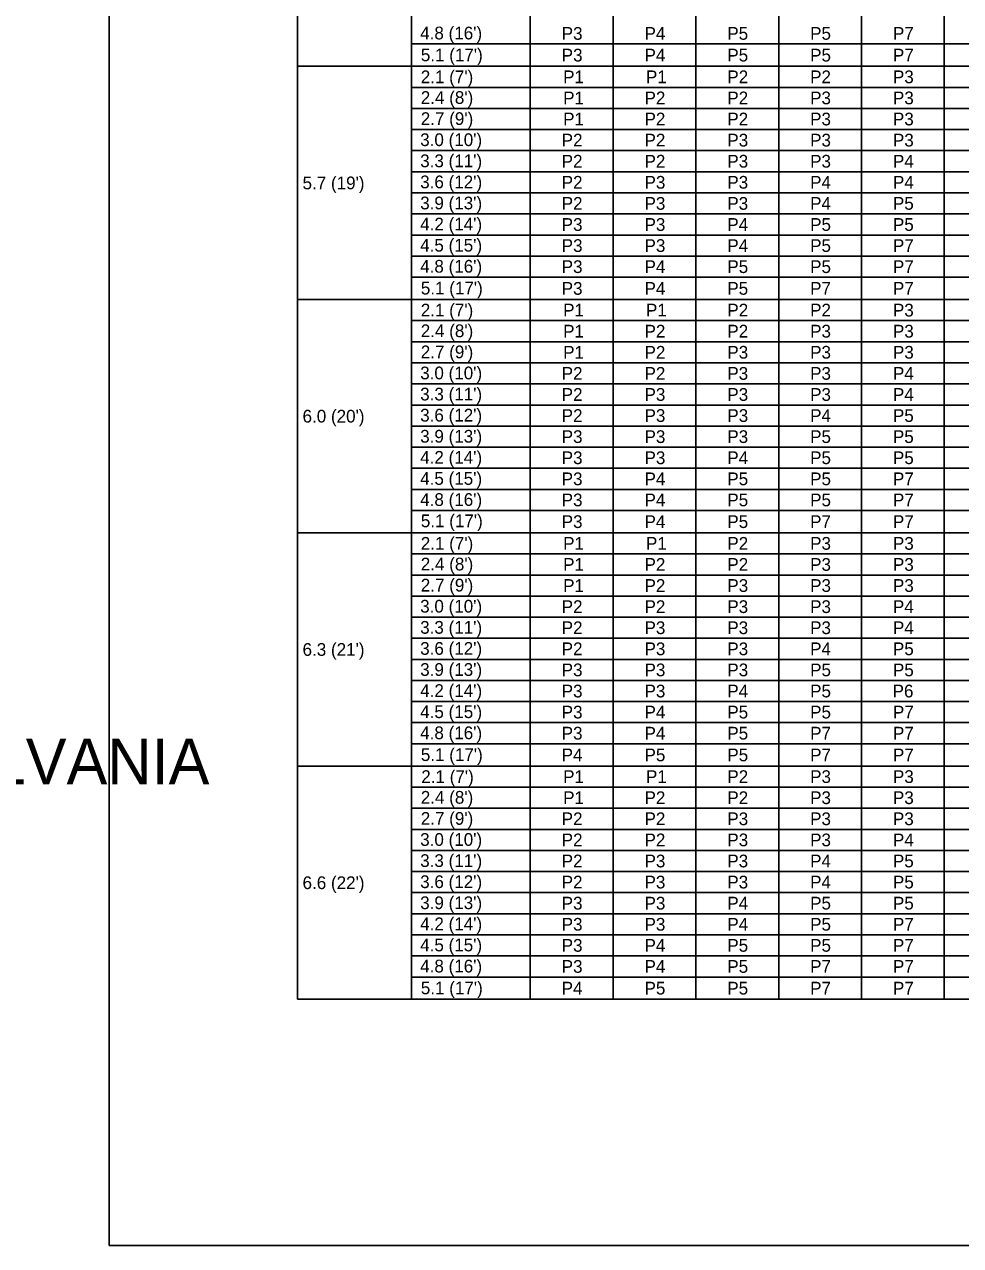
# Model space of a CAD drawing. Extents: x 637580 to 641008, y 294594 to 295782.
# Drawn here: x 639282.3 to 639502.8, y 295202.6 to 295490.5 of the extents above; entities that cross this region are included whole.
import ezdxf

# ---------------------------------------------------------------- set-up
doc = ezdxf.new("R2010")
doc.units = 0
doc.layers.add('1', color=7, linetype='Continuous')
doc.layers.add('2', color=7, linetype='Continuous')

msp = doc.modelspace()

# ---------------------------------------------------------------- linework, layer by layer
at = {"layer": '1'}
for p, q in [((639302.31, 295766.63), (639302.31, 295202.63)), ((639346.67, 295260.68), (639346.67, 295724.98)), ((639373.47, 295260.68), (639373.47, 295717.3)), ((639401.48, 295260.68), (639401.48, 295717.3)), ((639346.67, 295480.64), (639713.6, 295480.64)), ((639346.67, 295425.65), (639713.6, 295425.65)), ((639346.67, 295370.66), (639713.6, 295370.66)), ((639346.67, 295315.67), (639713.6, 295315.67)), ((639346.67, 295260.68), (639713.6, 295260.68)), ((640088.31, 295202.63), (639302.31, 295202.63)), ((639302.31, 295202.63), (639888.31, 295202.63))]:
    msp.add_line(p, q, dxfattribs=at)
at = {"layer": '2'}
for p, q in [((639401.48, 295260.68), (639401.48, 295717.3)), ((639420.98, 295260.68), (639420.98, 295709.96)), ((639440.49, 295260.68), (639440.49, 295709.96)), ((639460, 295260.68), (639460, 295709.96)), ((639479.51, 295260.68), (639479.51, 295709.96)), ((639499.01, 295260.68), (639499.01, 295709.96)), ((639373.47, 295485.9), (639713.6, 295485.9)), ((639373.47, 295475.66), (639713.6, 295475.66)), ((639373.47, 295470.69), (639713.6, 295470.69)), ((639373.47, 295465.72), (639713.6, 295465.72)), ((639373.47, 295460.75), (639713.6, 295460.75)), ((639373.47, 295455.77), (639713.6, 295455.77)), ((639373.47, 295450.8), (639713.6, 295450.8)), ((639373.47, 295445.83), (639713.6, 295445.83)), ((639373.47, 295440.86), (639713.6, 295440.86)), ((639373.47, 295435.88), (639713.6, 295435.88)), ((639373.47, 295430.91), (639713.6, 295430.91)), ((639373.47, 295420.67), (639713.6, 295420.67)), ((639373.47, 295415.7), (639713.6, 295415.7)), ((639373.47, 295410.73), (639713.6, 295410.73)), ((639373.47, 295405.76), (639713.6, 295405.76)), ((639373.47, 295400.78), (639713.6, 295400.78)), ((639373.47, 295395.81), (639713.6, 295395.81)), ((639373.47, 295390.84), (639713.6, 295390.84)), ((639373.47, 295385.87), (639713.6, 295385.87)), ((639373.47, 295380.89), (639713.6, 295380.89)), ((639373.47, 295375.92), (639713.6, 295375.92)), ((639373.47, 295365.68), (639713.6, 295365.68)), ((639373.47, 295360.71), (639713.6, 295360.71)), ((639373.47, 295355.74), (639713.6, 295355.74)), ((639373.47, 295350.77), (639713.6, 295350.77)), ((639373.47, 295345.79), (639713.6, 295345.79)), ((639373.47, 295340.82), (639713.6, 295340.82)), ((639373.47, 295335.85), (639713.6, 295335.85)), ((639373.47, 295330.88), (639713.6, 295330.88)), ((639373.47, 295325.9), (639713.6, 295325.9)), ((639373.47, 295320.93), (639713.6, 295320.93)), ((639373.47, 295310.69), (639713.6, 295310.69)), ((639373.47, 295305.72), (639713.6, 295305.72)), ((639373.47, 295300.75), (639713.6, 295300.75)), ((639373.47, 295295.78), (639713.6, 295295.78)), ((639373.47, 295290.8), (639713.6, 295290.8)), ((639373.47, 295285.83), (639713.6, 295285.83)), ((639373.47, 295280.86), (639713.6, 295280.86)), ((639373.47, 295275.89), (639713.6, 295275.89)), ((639373.47, 295270.91), (639713.6, 295270.91)), ((639373.47, 295265.94), (639713.6, 295265.94))]:
    msp.add_line(p, q, dxfattribs=at)

# ---------------------------------------------------------------- texts
at = {"layer": '1'}
for s, height, p in [("4.8 (16')", 3, (639375.54, 295486.98)), ('P3', 3, (639408.88, 295486.89)), ('P4', 3, (639428.39, 295486.89)), ('P5', 3, (639447.9, 295486.89)), ('P5', 3, (639467.4, 295486.89)), ('P7', 3, (639486.91, 295486.89)), ("5.1 (17')", 3, (639375.69, 295481.83)), ('P3', 3, (639408.88, 295481.77)), ('P4', 3, (639428.39, 295481.77)), ('P5', 3, (639447.9, 295481.77)), ('P5', 3, (639467.4, 295481.77)), ('P7', 3, (639486.91, 295481.77)), ("2.1 (7')", 3, (639375.68, 295476.65)), ('P1', 3, (639409.22, 295476.65)), ('P1', 3, (639428.73, 295476.65)), ('P2', 3, (639447.9, 295476.65)), ('P2', 3, (639467.4, 295476.65)), ('P3', 3, (639486.91, 295476.65)), ("2.4 (8')", 3, (639375.68, 295471.77)), ('P1', 3, (639409.22, 295471.68)), ('P2', 3, (639428.39, 295471.68)), ('P2', 3, (639447.9, 295471.68)), ('P3', 3, (639467.4, 295471.68)), ('P3', 3, (639486.91, 295471.68)), ("2.7 (9')", 3, (639375.68, 295466.8)), ('P1', 3, (639409.22, 295466.71)), ('P2', 3, (639428.39, 295466.71)), ('P2', 3, (639447.9, 295466.71)), ('P3', 3, (639467.4, 295466.71)), ('P3', 3, (639486.91, 295466.71)), ("3.0 (10')", 3, (639375.54, 295461.83)), ('P2', 3, (639408.88, 295461.73)), ('P2', 3, (639428.39, 295461.73)), ('P3', 3, (639447.9, 295461.73)), ('P3', 3, (639467.4, 295461.73)), ('P3', 3, (639486.91, 295461.73)), ("3.3 (11')", 3, (639375.54, 295456.85)), ('P2', 3, (639408.88, 295456.76)), ('P2', 3, (639428.39, 295456.76)), ('P3', 3, (639447.9, 295456.76)), ('P3', 3, (639467.4, 295456.76)), ('P4', 3, (639486.91, 295456.76)), ("5.7 (19')", 3, (639347.83, 295451.64)), ("3.6 (12')", 3, (639375.54, 295451.88)), ('P2', 3, (639408.88, 295451.79)), ('P3', 3, (639428.39, 295451.79)), ('P3', 3, (639447.9, 295451.79)), ('P4', 3, (639467.4, 295451.79)), ('P4', 3, (639486.91, 295451.79)), ("3.9 (13')", 3, (639375.54, 295446.91)), ('P2', 3, (639408.88, 295446.82)), ('P3', 3, (639428.39, 295446.82)), ('P3', 3, (639447.9, 295446.82)), ('P4', 3, (639467.4, 295446.82)), ('P5', 3, (639486.91, 295446.82)), ("4.2 (14')", 3, (639375.54, 295441.94)), ('P3', 3, (639408.88, 295441.84)), ('P3', 3, (639428.39, 295441.84)), ('P4', 3, (639447.9, 295441.84)), ('P5', 3, (639467.4, 295441.84)), ('P5', 3, (639486.91, 295441.84)), ("4.5 (15')", 3, (639375.54, 295436.96)), ('P3', 3, (639408.88, 295436.87)), ('P3', 3, (639428.39, 295436.87)), ('P4', 3, (639447.9, 295436.87)), ('P5', 3, (639467.4, 295436.87)), ('P7', 3, (639486.91, 295436.87)), ("4.8 (16')", 3, (639375.54, 295431.99)), ('P3', 3, (639408.88, 295431.9)), ('P4', 3, (639428.39, 295431.9)), ('P5', 3, (639447.9, 295431.9)), ('P5', 3, (639467.4, 295431.9)), ('P7', 3, (639486.91, 295431.9)), ("5.1 (17')", 3, (639375.69, 295426.84)), ('P3', 3, (639408.88, 295426.78)), ('P4', 3, (639428.39, 295426.78)), ('P5', 3, (639447.9, 295426.78)), ('P7', 3, (639467.4, 295426.78)), ('P7', 3, (639486.91, 295426.78)), ("2.1 (7')", 3, (639375.68, 295421.66)), ('P1', 3, (639409.22, 295421.66)), ('P1', 3, (639428.73, 295421.66)), ('P2', 3, (639447.9, 295421.66)), ('P2', 3, (639467.4, 295421.66)), ('P3', 3, (639486.91, 295421.66)), ("2.4 (8')", 3, (639375.68, 295416.78)), ('P1', 3, (639409.22, 295416.69)), ('P2', 3, (639428.39, 295416.69)), ('P2', 3, (639447.9, 295416.69)), ('P3', 3, (639467.4, 295416.69)), ('P3', 3, (639486.91, 295416.69)), ("2.7 (9')", 3, (639375.68, 295411.81)), ('P1', 3, (639409.22, 295411.72)), ('P2', 3, (639428.39, 295411.72)), ('P3', 3, (639447.9, 295411.72)), ('P3', 3, (639467.4, 295411.72)), ('P3', 3, (639486.91, 295411.72)), ("3.0 (10')", 3, (639375.54, 295406.84)), ('P2', 3, (639408.88, 295406.74)), ('P2', 3, (639428.39, 295406.74)), ('P3', 3, (639447.9, 295406.74)), ('P3', 3, (639467.4, 295406.74)), ('P4', 3, (639486.91, 295406.74)), ("3.3 (11')", 3, (639375.54, 295401.86)), ('P2', 3, (639408.88, 295401.77)), ('P3', 3, (639428.39, 295401.77)), ('P3', 3, (639447.9, 295401.77)), ('P3', 3, (639467.4, 295401.77)), ('P4', 3, (639486.91, 295401.77)), ("6.0 (20')", 3, (639347.83, 295396.65)), ("3.6 (12')", 3, (639375.54, 295396.89)), ('P2', 3, (639408.88, 295396.8)), ('P3', 3, (639428.39, 295396.8)), ('P3', 3, (639447.9, 295396.8)), ('P4', 3, (639467.4, 295396.8)), ('P5', 3, (639486.91, 295396.8)), ("3.9 (13')", 3, (639375.54, 295391.92)), ('P3', 3, (639408.88, 295391.83)), ('P3', 3, (639428.39, 295391.83)), ('P3', 3, (639447.9, 295391.83)), ('P5', 3, (639467.4, 295391.83)), ('P5', 3, (639486.91, 295391.83)), ("4.2 (14')", 3, (639375.54, 295386.95)), ('P3', 3, (639408.88, 295386.85)), ('P3', 3, (639428.39, 295386.85)), ('P4', 3, (639447.9, 295386.85)), ('P5', 3, (639467.4, 295386.85)), ('P5', 3, (639486.91, 295386.85)), ("4.5 (15')", 3, (639375.54, 295381.97)), ('P3', 3, (639408.88, 295381.88)), ('P4', 3, (639428.39, 295381.88)), ('P5', 3, (639447.9, 295381.88)), ('P5', 3, (639467.4, 295381.88)), ('P7', 3, (639486.91, 295381.88)), ("4.8 (16')", 3, (639375.54, 295377)), ('P3', 3, (639408.88, 295376.91)), ('P4', 3, (639428.39, 295376.91)), ('P5', 3, (639447.9, 295376.91)), ('P5', 3, (639467.4, 295376.91)), ('P7', 3, (639486.91, 295376.91)), ("5.1 (17')", 3, (639375.69, 295371.98)), ('P3', 3, (639408.88, 295371.79)), ('P4', 3, (639428.39, 295371.79)), ('P5', 3, (639447.9, 295371.79)), ('P7', 3, (639467.4, 295371.79)), ('P7', 3, (639486.91, 295371.79)), ("2.1 (7')", 3, (639375.68, 295366.67)), ('P1', 3, (639409.22, 295366.67)), ('P1', 3, (639428.73, 295366.67)), ('P2', 3, (639447.9, 295366.67)), ('P3', 3, (639467.4, 295366.67)), ('P3', 3, (639486.91, 295366.67)), ("2.4 (8')", 3, (639375.68, 295361.79)), ('P1', 3, (639409.22, 295361.7)), ('P2', 3, (639428.39, 295361.7)), ('P2', 3, (639447.9, 295361.7)), ('P3', 3, (639467.4, 295361.7)), ('P3', 3, (639486.91, 295361.7)), ("2.7 (9')", 3, (639375.68, 295356.82)), ('P1', 3, (639409.22, 295356.73)), ('P2', 3, (639428.39, 295356.73)), ('P3', 3, (639447.9, 295356.73)), ('P3', 3, (639467.4, 295356.73)), ('P3', 3, (639486.91, 295356.73)), ("3.0 (10')", 3, (639375.54, 295351.85)), ('P2', 3, (639408.88, 295351.75)), ('P2', 3, (639428.39, 295351.75)), ('P3', 3, (639447.9, 295351.75)), ('P3', 3, (639467.4, 295351.75)), ('P4', 3, (639486.91, 295351.75)), ("3.3 (11')", 3, (639375.54, 295346.87)), ('P2', 3, (639408.88, 295346.78)), ('P3', 3, (639428.39, 295346.78)), ('P3', 3, (639447.9, 295346.78)), ('P3', 3, (639467.4, 295346.78)), ('P4', 3, (639486.91, 295346.78)), ("6.3 (21')", 3, (639347.83, 295341.66)), ("3.6 (12')", 3, (639375.54, 295341.9)), ('P2', 3, (639408.88, 295341.81)), ('P3', 3, (639428.39, 295341.81)), ('P3', 3, (639447.9, 295341.81)), ('P4', 3, (639467.4, 295341.81)), ('P5', 3, (639486.91, 295341.81)), ("3.9 (13')", 3, (639375.54, 295336.93)), ('P3', 3, (639408.88, 295336.84)), ('P3', 3, (639428.39, 295336.84)), ('P3', 3, (639447.9, 295336.84)), ('P5', 3, (639467.4, 295336.84)), ('P5', 3, (639486.91, 295336.84)), ("4.2 (14')", 3, (639375.54, 295331.96)), ('P3', 3, (639408.88, 295331.86)), ('P3', 3, (639428.39, 295331.86)), ('P4', 3, (639447.9, 295331.86)), ('P5', 3, (639467.4, 295331.86)), ('P6', 3, (639486.83, 295331.86)), ("4.5 (15')", 3, (639375.54, 295326.98)), ('P3', 3, (639408.88, 295326.89)), ('P4', 3, (639428.39, 295326.89)), ('P5', 3, (639447.9, 295326.89)), ('P5', 3, (639467.4, 295326.89)), ('P7', 3, (639486.91, 295326.89)), ("4.8 (16')", 3, (639375.54, 295322.01)), ('P3', 3, (639408.88, 295321.92)), ('P4', 3, (639428.39, 295321.92)), ('P5', 3, (639447.9, 295321.92)), ('P7', 3, (639467.4, 295321.92)), ('P7', 3, (639486.91, 295321.92)), ('COMMONWEALTH OF PENNSYLVANIA', 10.7828, (639059.9, 295311.36)), ("5.1 (17')", 3, (639375.69, 295316.86)), ('P4', 3, (639408.88, 295316.8)), ('P5', 3, (639428.39, 295316.8)), ('P5', 3, (639447.9, 295316.8)), ('P7', 3, (639467.4, 295316.8)), ('P7', 3, (639486.91, 295316.8)), ("2.1 (7')", 3, (639375.8, 295311.68)), ('P1', 3, (639409.22, 295311.68)), ('P1', 3, (639428.73, 295311.68)), ('P2', 3, (639447.9, 295311.68)), ('P3', 3, (639467.4, 295311.68)), ('P3', 3, (639486.91, 295311.68)), ("2.4 (8')", 3, (639375.68, 295306.8)), ('P1', 3, (639409.22, 295306.71)), ('P2', 3, (639428.39, 295306.71)), ('P2', 3, (639447.9, 295306.71)), ('P3', 3, (639467.4, 295306.71)), ('P3', 3, (639486.91, 295306.71)), ("2.7 (9')", 3, (639375.68, 295301.83)), ('P2', 3, (639408.88, 295301.74)), ('P2', 3, (639428.39, 295301.74)), ('P3', 3, (639447.9, 295301.74)), ('P3', 3, (639467.4, 295301.74)), ('P3', 3, (639486.91, 295301.74)), ("3.0 (10')", 3, (639375.54, 295296.86)), ('P2', 3, (639408.88, 295296.76)), ('P2', 3, (639428.39, 295296.76)), ('P3', 3, (639447.9, 295296.76)), ('P3', 3, (639467.4, 295296.76)), ('P4', 3, (639486.91, 295296.76)), ("3.3 (11')", 3, (639375.54, 295291.88)), ('P2', 3, (639408.88, 295291.79)), ('P3', 3, (639428.39, 295291.79)), ('P3', 3, (639447.9, 295291.79)), ('P4', 3, (639467.4, 295291.79)), ('P5', 3, (639486.91, 295291.79)), ("6.6 (22')", 3, (639347.83, 295286.67)), ("3.6 (12')", 3, (639375.54, 295286.91)), ('P2', 3, (639408.88, 295286.82)), ('P3', 3, (639428.39, 295286.82)), ('P3', 3, (639447.9, 295286.82)), ('P4', 3, (639467.4, 295286.82)), ('P5', 3, (639486.91, 295286.82)), ("3.9 (13')", 3, (639375.54, 295281.94)), ('P3', 3, (639408.88, 295281.85)), ('P3', 3, (639428.39, 295281.85)), ('P4', 3, (639447.9, 295281.85)), ('P5', 3, (639467.4, 295281.85)), ('P5', 3, (639486.91, 295281.85)), ("4.2 (14')", 3, (639375.54, 295276.97)), ('P3', 3, (639408.88, 295276.87)), ('P3', 3, (639428.39, 295276.87)), ('P4', 3, (639447.9, 295276.87)), ('P5', 3, (639467.4, 295276.87)), ('P7', 3, (639486.91, 295276.87)), ("4.5 (15')", 3, (639375.54, 295271.99)), ('P3', 3, (639408.88, 295271.9)), ('P4', 3, (639428.39, 295271.9)), ('P5', 3, (639447.9, 295271.9)), ('P5', 3, (639467.4, 295271.9)), ('P7', 3, (639486.91, 295271.9)), ("4.8 (16')", 3, (639375.54, 295267.02)), ('P3', 3, (639408.88, 295266.93)), ('P4', 3, (639428.39, 295266.93)), ('P5', 3, (639447.9, 295266.93)), ('P7', 3, (639467.4, 295266.93)), ('P7', 3, (639486.91, 295266.93)), ("5.1 (17')", 3, (639375.69, 295261.87)), ('P4', 3, (639408.88, 295261.81)), ('P5', 3, (639428.39, 295261.81)), ('P5', 3, (639447.9, 295261.81)), ('P7', 3, (639467.4, 295261.81)), ('P7', 3, (639486.91, 295261.81))]:
    msp.add_text(s, height=height, dxfattribs=at).set_placement(p)

doc.saveas('drawing.dxf')
